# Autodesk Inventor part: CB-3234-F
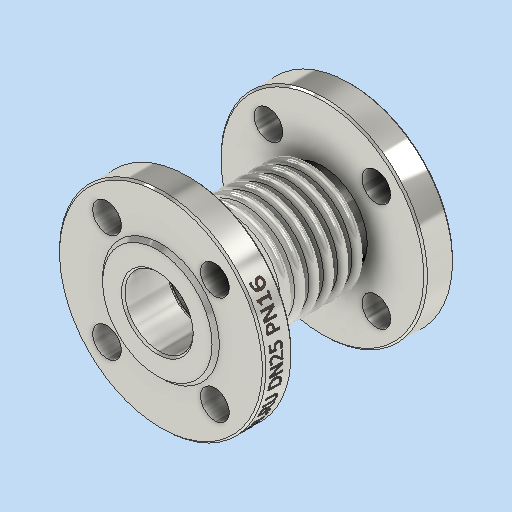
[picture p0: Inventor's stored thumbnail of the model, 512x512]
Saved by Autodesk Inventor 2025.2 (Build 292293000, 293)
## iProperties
Company: DN.RU
Created: 2026-04
Part Number: CB-3234-F
Material: Типовые
Document SubType Name: Modeling
Designer: DN.RU
Density: 8.81307 g/cm^3
Appearance: По умолчанию
Description: D140-02110
Mass: 2700 g
Surface Area: 1172.92 cm^2
Volume: 306.363 cm^3
Author: DN.RU
Title: Компенсатор сильфонный осевой DN.ru Ду25 Ру16
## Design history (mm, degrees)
sketch "Эскиз1"
  geometry: L1 (0, 0)-(0, -55); L2 (23, -55)-(23, 0); L3 (23, 0)-(0, 0); L4 (23, 0)-(23, -4); L5 (18, -4)-(28, -4); L6 (18, -6.5)-(28, -6.5); L7 (28, -1.5)-(18, -1.5); L8 (28, -5.5)-(18, -5.5); L9 (18, -2.5)-(28, -2.5); L10 (28, -9.5)-(18, -9.5); L11 (18, -10.5)-(28, -10.5); L12 (18, -12)-(28, -12); L13 (18, -14.5)-(28, -14.5); L14 (28, -13.5)-(18, -13.5); L15 (28, -17.5)-(18, -17.5); L16 (18, -18.5)-(28, -18.5); L17 (18, -20)-(28, -20); L18 (18, -22.5)-(28, -22.5); L19 (28, -21.5)-(18, -21.5); L20 (28, -25.5)-(18, -25.5); L21 (18, -26.5)-(28, -26.5); L22 (18, -28)-(28, -28); L23 (18, -30.5)-(28, -30.5); L24 (28, -29.5)-(18, -29.5); L25 (0, -55)-(23, -55); L26 (23, -55)-(19, -55); L27 (23, -25.5)-(22, -25.5); L28 (19, -55)-(19, -29.5); L29 (23, -26.5)-(22, -26.5); L30 (22, -26.5)-(22, -21.5); L31 (23, -18.5)-(22, -18.5); L32 (22, -18.5)-(22, -13.5); L33 (23, -10.5)-(22, -10.5); L34 (22, -10.5)-(22, -5.5); L35 (23, -2.5)-(22, -2.5); L36 (22, -2.5)-(22, 0); L37 (0, -55)-(0, -37); L38 (0, -37)-(57.5, -37); L39 (57.5, -37)-(57.5, -55); L40 (57.5, -55)-(0, -55); L41 (23, -37)-(23, -47); L42 (23, -47)-(25, -47); L43 (25, -47)-(25, -37); L44 (25, -37)-(23, -37); A1 r 2.5 centre (18, -4) between (18, -1.5) and (18, -6.5); A2 r 2.5 centre (28, -4) between (28, -6.5) and (28, -1.5); A3 r 1.5 centre (18, -4) between (18, -2.5) and (18, -5.5); A4 r 1.5 centre (28, -4) between (28, -5.5) and (28, -2.5); A5 r 1.5 centre (18, -12) between (18, -10.5) and (18, -13.5); A6 r 2.5 centre (18, -12) between (18, -9.5) and (18, -14.5); A7 r 1.5 centre (28, -12) between (28, -13.5) and (28, -10.5); A8 r 2.5 centre (28, -12) between (28, -14.5) and (28, -9.5); A9 r 1.5 centre (18, -20) between (18, -18.5) and (18, -21.5); A10 r 2.5 centre (18, -20) between (18, -17.5) and (18, -22.5); A11 r 1.5 centre (28, -20) between (28, -21.5) and (28, -18.5); A12 r 2.5 centre (28, -20) between (28, -22.5) and (28, -17.5); A13 r 1.5 centre (18, -28) between (18, -26.5) and (18, -29.5); A14 r 2.5 centre (18, -28) between (18, -25.5) and (18, -30.5); A15 r 1.5 centre (28, -28) between (28, -29.5) and (28, -26.5); A16 r 2.5 centre (28, -28) between (28, -30.5) and (28, -25.5); 20 further points
  constraints: 96 end point, 32 point on circle, 19 point on line, 16 centre point, 7 parallel, 7 perpendicular, 6 midpoint, 4 tangent, 2 vertical, 1 horizontal, 69 other
  dimensions: "d0" = 55 distance of L1.start L1.end; "d3" = 4 distance of L2.end L4.end; "d4" = 5 distance of L4.end L5.end; "d5" = 5 diameter of A2; "d6" = 1 distance between parallel lines of L6 L8; "d9" = 8 distance of L4.end point (23, -12); "d15" = 1 distance of L27.start L27.end; "d16" = 1 distance of L29.start L29.end; "d17" = 1 distance of L31.start L31.end; "d18" = 1 distance of L33.start L33.end; "d19" = 1 distance of L35.start L35.end; "d27" = 19 distance between parallel lines of L1 L28; "d28" = 4 distance between parallel lines of L2 L28; "d29" = 18 distance of L1.end L37.end; "d30" = 57.5 distance of L37.end L38.end; "d31" = 10 distance of L41.start L41.end; "d32" = 2 distance of L42.end L41.end
revolve "Вращение1" sketch "Эскиз1" stored, may be unused: angle "d20" = 360 deg
sketch "Эскиз3" dims "d33" = 85
  geometry: L1 (0, 0)-(54.414, 54.414); L2 (0, 0)-(76.954, 0); C1 r 8 at (30.052, 30.052); C2 r 8 at (-30.052, 30.052); C3 r 8 at (-30.052, -30.052); C4 r 8 at (30.052, -30.052); C5 r 19 at (0, 0) reference; C6 r 32.5 at (0, 0); C7 r 57.5 at (0, 0) reference; 1 further point
  constraints: 5 centre point, 4 end point, 2 coincident, 1 equal length, 1 horizontal, 1 point on line, 12 other
  dimensions: "d34" = 45 deg angle of L2 L1; "d35" = 16 diameter of C1; "d38" = 360 deg dimension on point (0, 0) C1.centre (derived); "d40" = 65 diameter of C6
  node "Эскиз — круговой массив1" dims "d38" = 360 deg (derived)
extrude "Выдавливание1" cut sketch "Эскиз3" stored distance "d41" = 10; taper "d42" = 0 deg
extrude "Выдавливание2" cut sketch "Эскиз3" distance "d43" = 2; taper "d44" = 0 deg
chamfer "Фаска2" distance "d45" = 2; stored, may be unused: second distance "d46" = 2, angle "d47" = 45 deg
chamfer "Фаска3" distance "d48" = 1; stored, may be unused: second distance "d49" = 2, angle "d50" = 45 deg
mirror "Зеркальное отражение2"
fillet "Сопряжение2" dims "d51" = 1
node "РабПлоскость2"
sketch "Эскиз4"
  geometry: L1 (-44.383, 3.589)-(46.395, 3.589); L2 (46.395, 3.589)-(46.395, 0.413); L3 (46.395, 0.413)-(-44.383, 0.413); L4 (-44.383, 0.413)-(-44.383, 3.589); 1 further point
  constraints: 2 other
feature "Рельеф2" sketch "Эскиз4" dims "d52" = 0.1, "d53" = 0
node "Твердое тело1"
node "Эскиз — прямоугольный массив1" dims "d9" = 8, "d12" = 10
